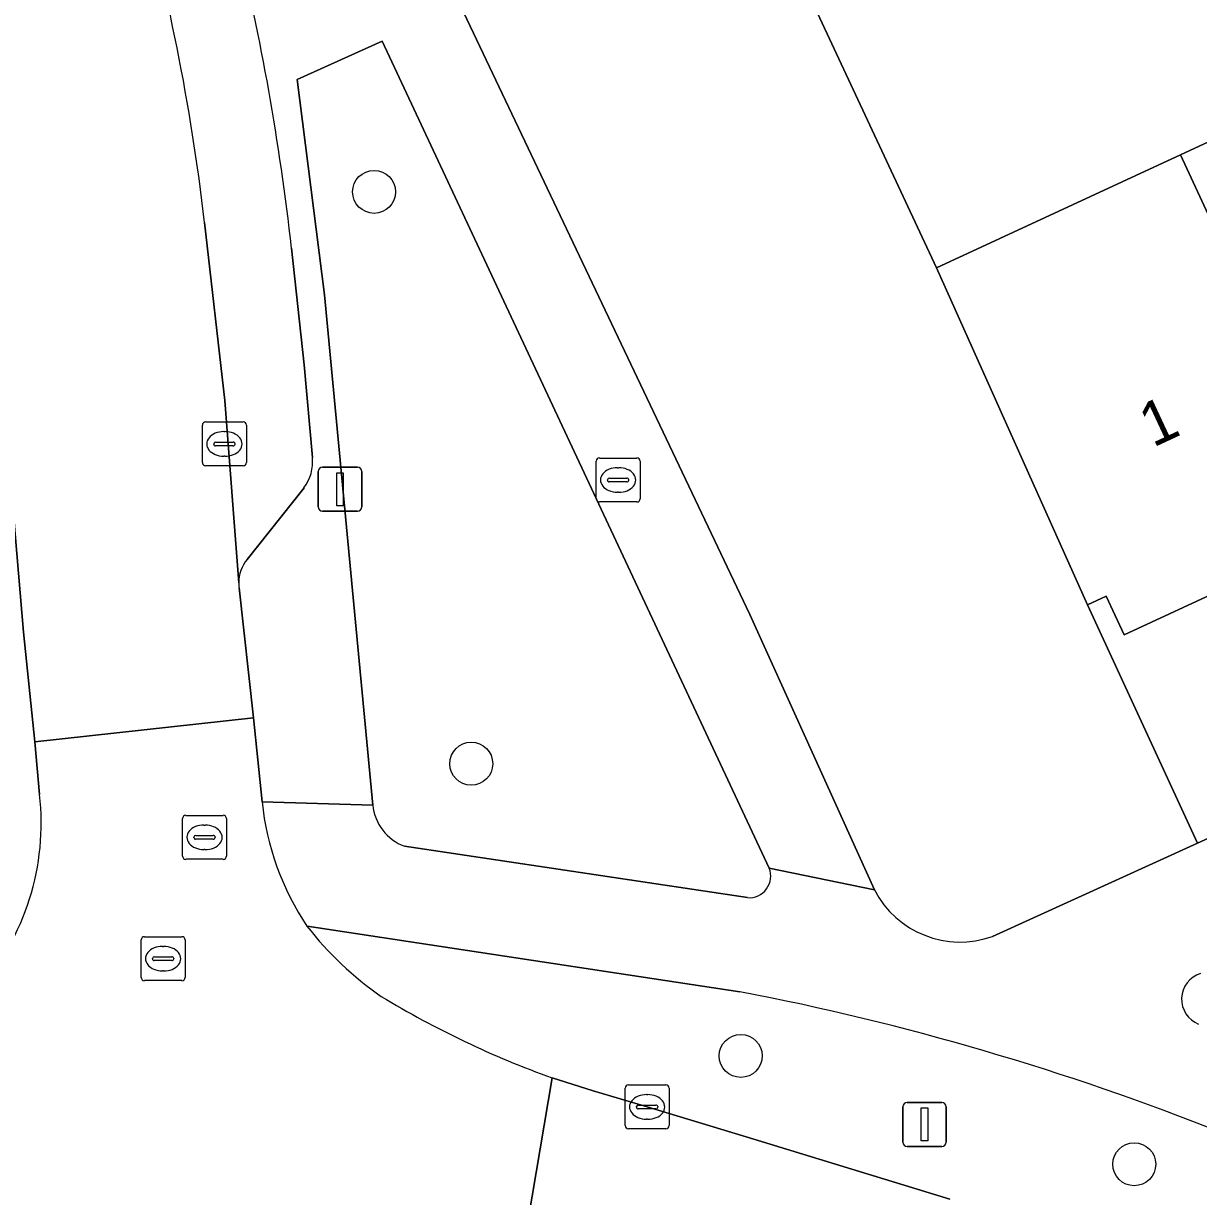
# Model space of a CAD drawing. Extents: x 160030 to 160839, y 385325 to 386450.
# Drawn here: x 160443.86 to 160470.59, y 386074.84 to 386101.52 of the extents above; entities that cross this region are included whole.
import ezdxf

# ---------------------------------------------------------------- set-up
doc = ezdxf.new("R2010")
doc.units = 0
for name, color, linetype in [('IMGEO_Boom', 7, 'Continuous'), ('IMGEO_Brandkraan', 7, 'Continuous'), ('IMGEO_Erf', 7, 'Continuous'), ('IMGEO_Groenvoorziening', 7, 'Continuous'), ('IMGEO_Kolk', 7, 'Continuous'), ('IMGEO_Lichtmast', 7, 'Continuous'), ('IMGEO_Pand', 7, 'Continuous'), ('IMGEO_Pand_nummerreeks', 7, 'Continuous'), ('IMGEO_Parkeervlak_open', 7, 'Continuous'), ('IMGEO_Rijbaan_lokaal_open', 7, 'Continuous'), ('IMGEO_Rioolput', 7, 'Continuous'), ('IMGEO_Voetpad_open', 7, 'Continuous')]:
    doc.layers.add(name, color=color, linetype=linetype)

msp = doc.modelspace()

# ---------------------------------------------------------------- linework, layer by layer
at = {"layer": 'IMGEO_Boom'}
for centre in [(160451.838, 386097.694), (160454.047, 386084.687), (160460.175, 386078.041), (160469.124, 386075.577)]:
    msp.add_circle(centre, 0.489, dxfattribs=at)
at = {"layer": 'IMGEO_Brandkraan'}
for p, q in [((160456.886, 386090.714), (160456.886, 386091.566)), ((160456.961, 386091.64), (160457.813, 386091.64)), ((160457.887, 386091.566), (160457.887, 386090.714)), ((160457.188, 386091.183), (160457.586, 386091.183)), ((160457.374, 386091.42), (160457.399, 386091.42)), ((160457.145, 386091.134), (160457.145, 386091.146)), ((160457.583, 386091.097), (160457.185, 386091.097)), ((160457.629, 386091.146), (160457.629, 386091.134)), ((160457.397, 386090.86), (160457.372, 386090.86)), ((160457.813, 386090.64), (160456.961, 386090.64))]:
    msp.add_line(p, q, dxfattribs=at)
for points in [[(160456.886, 386090.714), (160456.886, 386091.566)], [(160456.961, 386091.64), (160457.813, 386091.64)], [(160457.887, 386091.566), (160457.887, 386090.714)], [(160457.813, 386090.64), (160456.961, 386090.64)]]:
    msp.add_lwpolyline(points, dxfattribs=at)
for centre, radius, start, end in [((160456.963, 386091.564), 0.0765, 91.552, 178.448), ((160456.963, 386091.564), 0.0765, 91.552, 178.448), ((160457.811, 386091.564), 0.0765, 1.552, 88.448), ((160457.811, 386091.564), 0.0765, 1.552, 88.448), ((160457.185, 386091.143), 0.0403, 85.8775, 175.7526), ((160457.59, 386091.145), 0.0386, 1.7309, 96.639), ((160457.182, 386091.133), 0.0366, 178.938, 274.7102), ((160457.586, 386091.14), 0.043, 264.8664, 352.4533), ((160456.963, 386090.716), 0.0765, 181.552, 268.448), ((160456.963, 386090.716), 0.0765, 181.552, 268.448), ((160457.811, 386090.716), 0.0765, 271.552, 358.448), ((160457.811, 386090.716), 0.0765, 271.552, 358.448)]:
    msp.add_arc(centre, radius, start, end, dxfattribs=at)
for centre, major_axis, ratio, start_param, end_param in [((160457.373, 386091.14), (-0.387, 0.002), 0.722429, 4.712389, 7.853982), ((160457.398, 386091.14), (-0.39, 0.002), 0.717154, 1.570796, 4.712389)]:
    msp.add_ellipse(centre, major_axis=major_axis, ratio=ratio, start_param=start_param, end_param=end_param, dxfattribs=at)
at = {"layer": 'IMGEO_Erf'}
for points in [[(160474.661, 386111.537), (160468.204, 386108.702), (160469.751, 386105.389), (160467.465, 386104.321), (160465.268, 386103.296), (160463.721, 386106.609), (160460.404, 386105.012), (160464.625, 386095.964), (160469.161, 386098.069), (160470.175, 386098.539), (160475.678, 386101.093)], [(160472.199, 386089.152), (160468.893, 386087.619), (160468.487, 386088.495), (160468.06, 386088.297), (160470.559, 386082.88), (160479.048, 386086.745)]]:
    msp.add_lwpolyline(points, dxfattribs=at)
at = {"layer": 'IMGEO_Groenvoorziening'}
for points in [[(160464.625, 386095.964), (160460.404, 386105.012), (160453.801, 386101.927), (160460.384, 386088.081), (160463.214, 386081.817)], [(160460.825, 386082.312), (160452.021, 386101.119), (160450.089, 386100.248), (160450.712, 386095.349), (160451.809, 386083.747)], [(160465.902, 386080.76), (160470.559, 386082.88), (160468.06, 386088.297), (160464.625, 386095.964)], [(160452.528, 386082.809), (160460.327, 386081.64)], [(160460.154, 386079.501), (160450.312, 386080.99)], [(160455.889, 386077.541), (160456.822, 386077.249), (160458.047, 386076.88), (160460.475, 386076.143), (160464.932, 386074.783)]]:
    msp.add_lwpolyline(points, dxfattribs=at)
for centre, radius, start, end in [((160452.911, 386083.847), 1.106, 185.1833, 249.7588), ((160460.364, 386082.133), 0.494, 265.6625, 21.2553), ((160465.162, 386082.823), 2.192, 207.3267, 289.7409), ((160456.517, 386085.857), 7.886, 218.108, 235.0637), ((160470.81, 386079.33), 0.609, 107.0053, 248.6087), ((160448.682, 386019.999), 60.598, 68.26831, 79.08732), ((160463.201, 386097.909), 21.641, 238.8319, 250.2517)]:
    msp.add_arc(centre, radius, start, end, dxfattribs=at)
at = {"layer": 'IMGEO_Kolk'}
for p, q in [((160447.932, 386091.534), (160447.932, 386092.386)), ((160448.007, 386092.46), (160448.859, 386092.46)), ((160448.933, 386092.386), (160448.933, 386091.534)), ((160448.234, 386092.003), (160448.632, 386092.003)), ((160448.42, 386092.24), (160448.445, 386092.24)), ((160448.191, 386091.954), (160448.191, 386091.966)), ((160448.629, 386091.917), (160448.231, 386091.917)), ((160448.675, 386091.966), (160448.675, 386091.954)), ((160448.859, 386091.46), (160448.007, 386091.46)), ((160448.443, 386091.68), (160448.418, 386091.68)), ((160457.546, 386076.454), (160457.546, 386077.306)), ((160457.621, 386077.38), (160458.473, 386077.38)), ((160458.547, 386077.306), (160458.547, 386076.454)), ((160458.034, 386077.16), (160458.059, 386077.16)), ((160457.805, 386076.874), (160457.805, 386076.886)), ((160458.243, 386076.837), (160457.845, 386076.837)), ((160457.848, 386076.923), (160458.246, 386076.923)), ((160458.289, 386076.886), (160458.289, 386076.874)), ((160458.057, 386076.6), (160458.032, 386076.6)), ((160458.473, 386076.38), (160457.621, 386076.38))]:
    msp.add_line(p, q, dxfattribs=at)
for points in [[(160447.932, 386091.534), (160447.932, 386092.386)], [(160448.007, 386092.46), (160448.859, 386092.46)], [(160448.933, 386092.386), (160448.933, 386091.534)], [(160448.859, 386091.46), (160448.007, 386091.46)], [(160457.546, 386076.454), (160457.546, 386077.306)], [(160457.621, 386077.38), (160458.473, 386077.38)], [(160458.547, 386077.306), (160458.547, 386076.454)], [(160458.473, 386076.38), (160457.621, 386076.38)]]:
    msp.add_lwpolyline(points, dxfattribs=at)
for centre, radius, start, end in [((160448.009, 386092.384), 0.0765, 91.552, 178.448), ((160448.009, 386092.384), 0.0765, 91.552, 178.448), ((160448.857, 386092.384), 0.0765, 1.552, 88.448), ((160448.857, 386092.384), 0.0765, 1.552, 88.448), ((160448.231, 386091.963), 0.0403, 85.8775, 175.7526), ((160448.636, 386091.965), 0.0386, 1.7309, 96.639), ((160448.228, 386091.953), 0.0366, 178.938, 274.7102), ((160448.632, 386091.96), 0.043, 264.8664, 352.4533), ((160448.009, 386091.536), 0.0765, 181.552, 268.448), ((160448.009, 386091.536), 0.0765, 181.552, 268.448), ((160448.857, 386091.536), 0.0765, 271.552, 358.448), ((160448.857, 386091.536), 0.0765, 271.552, 358.448), ((160457.623, 386077.304), 0.0765, 91.552, 178.448), ((160457.623, 386077.304), 0.0765, 91.552, 178.448), ((160458.471, 386077.304), 0.0765, 1.552, 88.448), ((160458.471, 386077.304), 0.0765, 1.552, 88.448), ((160457.845, 386076.883), 0.0403, 85.8775, 175.7526), ((160457.842, 386076.873), 0.0366, 178.938, 274.7102), ((160458.246, 386076.88), 0.043, 264.8664, 352.4533), ((160458.25, 386076.885), 0.0386, 1.7309, 96.639), ((160457.623, 386076.456), 0.0765, 181.552, 268.448), ((160457.623, 386076.456), 0.0765, 181.552, 268.448), ((160458.471, 386076.456), 0.0765, 271.552, 358.448), ((160458.471, 386076.456), 0.0765, 271.552, 358.448)]:
    msp.add_arc(centre, radius, start, end, dxfattribs=at)
for centre, major_axis, ratio, start_param, end_param in [((160448.419, 386091.96), (-0.387, 0.002), 0.722429, 4.712389, 7.853982), ((160448.444, 386091.96), (-0.39, 0.002), 0.717154, 1.570796, 4.712389), ((160458.033, 386076.88), (-0.387, 0.002), 0.722429, 4.712389, 7.853982), ((160458.058, 386076.88), (-0.39, 0.002), 0.717154, 1.570796, 4.712389)]:
    msp.add_ellipse(centre, major_axis=major_axis, ratio=ratio, start_param=start_param, end_param=end_param, dxfattribs=at)
at = {"layer": 'IMGEO_Lichtmast'}
for p, q in [((160450.568, 386090.53), (160450.568, 386091.33)), ((160450.568, 386091.33), (160450.568, 386090.53)), ((160450.668, 386091.43), (160451.458, 386091.43)), ((160451.458, 386091.43), (160450.668, 386091.43)), ((160451.558, 386091.33), (160451.558, 386090.53)), ((160451.558, 386090.53), (160451.558, 386091.33)), ((160451.458, 386090.43), (160450.668, 386090.43)), ((160450.668, 386090.43), (160451.458, 386090.43)), ((160463.859, 386076.081), (160463.859, 386076.881)), ((160463.859, 386076.881), (160463.859, 386076.081)), ((160463.959, 386076.981), (160464.749, 386076.981)), ((160464.749, 386076.981), (160463.959, 386076.981)), ((160464.849, 386076.881), (160464.849, 386076.081)), ((160464.849, 386076.081), (160464.849, 386076.881)), ((160464.749, 386075.981), (160463.959, 386075.981)), ((160463.959, 386075.981), (160464.749, 386075.981))]:
    msp.add_line(p, q, dxfattribs=at)
for points in [[(160450.988, 386091.305), (160451.138, 386091.305), (160451.138, 386090.555), (160450.988, 386090.555), (160450.988, 386091.305)], [(160464.279, 386076.856), (160464.429, 386076.856), (160464.429, 386076.106), (160464.279, 386076.106), (160464.279, 386076.856)]]:
    msp.add_lwpolyline(points, dxfattribs=at)
for centre, start, end in [((160450.668, 386091.33), 90, 180), ((160450.668, 386091.33), 90, 180), ((160451.458, 386091.33), 0, 90), ((160451.458, 386091.33), 360, 90), ((160450.668, 386090.53), 180, 270), ((160450.668, 386090.53), 180, 270), ((160451.458, 386090.53), 270, 0), ((160451.458, 386090.53), 270, 0), ((160463.959, 386076.881), 90, 180), ((160463.959, 386076.881), 90, 180), ((160464.749, 386076.881), 0, 90), ((160464.749, 386076.881), 360, 90), ((160463.959, 386076.081), 180, 270), ((160463.959, 386076.081), 180, 270), ((160464.749, 386076.081), 270, 0), ((160464.749, 386076.081), 270, 0)]:
    msp.add_arc(centre, 0.1, start, end, dxfattribs=at)
at = {"layer": 'IMGEO_Pand'}
for points in [[(160470.175, 386098.539), (160473.671, 386090.996), (160475.584, 386091.883), (160476.011, 386090.96), (160479.606, 386092.627), (160475.678, 386101.093)], [(160464.625, 386095.964), (160468.06, 386088.297), (160468.487, 386088.495), (160468.893, 386087.619), (160472.199, 386089.152), (160471.756, 386090.108), (160473.671, 386090.996), (160470.175, 386098.539), (160469.161, 386098.069)]]:
    msp.add_lwpolyline(points, close=True, dxfattribs=at)
at = {"layer": 'IMGEO_Parkeervlak_open'}
for points in [[(160443.865, 386087.68), (160443.212, 386095.286), (160442.948, 386097.648)], [(160447.982, 386096.997), (160448.44, 386092.949), (160448.758, 386088.803)], [(160450.436, 386091.651), (160450.245, 386093.762), (160449.961, 386096.41)], [(160448.949, 386089.332), (160450.244, 386090.965)]]:
    msp.add_lwpolyline(points, dxfattribs=at)
for centre, radius, start, end in [((160391.854, 386089.795), 58.485, 10.04637, 17.00413), ((160399.418, 386091.395), 48.886, 6.5797, 16.001), ((160391.996, 386089.854), 58.334, 6.45274, 10.01315), ((160449.452, 386091.556), 0.988, 323.2408, 5.4871), ((160449.589, 386088.802), 0.831, 140.3642, 179.9307)]:
    msp.add_arc(centre, radius, start, end, dxfattribs=at)
at = {"layer": 'IMGEO_Rijbaan_lokaal_open'}
for points in [[(160442.948, 386097.648), (160443.212, 386095.286), (160443.865, 386087.68), (160444.125, 386085.184), (160449.099, 386085.729), (160448.766, 386088.69)], [(160448.758, 386088.803), (160448.44, 386092.949), (160447.982, 386096.997)], [(160449.289, 386083.818), (160449.099, 386085.729), (160444.125, 386085.184), (160444.231, 386083.987)], [(160454.879, 386071.573), (160455.889, 386077.541)], [(160464.932, 386074.783), (160460.475, 386076.143), (160458.047, 386076.88), (160456.822, 386077.249), (160455.889, 386077.541), (160454.879, 386071.573), (160456.59, 386071.254)]]:
    msp.add_lwpolyline(points, dxfattribs=at)
for centre, radius, start, end in [((160399.418, 386091.395), 48.886, 6.5797, 16.001), ((160449.549, 386088.802), 0.791, 179.9436, 188.1555), ((160438.533, 386083.335), 5.735, 270.3865, 6.5305), ((160455.565, 386084.489), 6.312, 186.1048, 213.6693), ((160456.517, 386085.857), 7.886, 218.108, 235.0637), ((160463.201, 386097.909), 21.641, 238.8319, 250.2517)]:
    msp.add_arc(centre, radius, start, end, dxfattribs=at)
at = {"layer": 'IMGEO_Rioolput'}
for p, q in [((160447.481, 386082.586), (160447.481, 386083.438)), ((160447.556, 386083.512), (160448.408, 386083.512)), ((160448.482, 386083.438), (160448.482, 386082.586)), ((160447.969, 386083.292), (160447.994, 386083.292)), ((160447.74, 386083.006), (160447.74, 386083.018)), ((160448.178, 386082.969), (160447.78, 386082.969)), ((160447.783, 386083.055), (160448.181, 386083.055)), ((160448.224, 386083.018), (160448.224, 386083.006)), ((160447.992, 386082.732), (160447.967, 386082.732)), ((160448.408, 386082.512), (160447.556, 386082.512)), ((160446.539, 386079.826), (160446.539, 386080.678)), ((160446.614, 386080.752), (160447.466, 386080.752)), ((160447.027, 386080.532), (160447.052, 386080.532)), ((160447.54, 386080.678), (160447.54, 386079.826)), ((160446.798, 386080.246), (160446.798, 386080.258)), ((160446.841, 386080.295), (160447.239, 386080.295)), ((160447.282, 386080.258), (160447.282, 386080.246)), ((160447.236, 386080.209), (160446.838, 386080.209)), ((160447.05, 386079.972), (160447.025, 386079.972)), ((160447.466, 386079.752), (160446.614, 386079.752))]:
    msp.add_line(p, q, dxfattribs=at)
for points in [[(160447.481, 386082.586), (160447.481, 386083.438)], [(160447.556, 386083.512), (160448.408, 386083.512)], [(160448.482, 386083.438), (160448.482, 386082.586)], [(160448.408, 386082.512), (160447.556, 386082.512)], [(160446.539, 386079.826), (160446.539, 386080.678)], [(160446.614, 386080.752), (160447.466, 386080.752)], [(160447.54, 386080.678), (160447.54, 386079.826)], [(160447.466, 386079.752), (160446.614, 386079.752)]]:
    msp.add_lwpolyline(points, dxfattribs=at)
for centre, radius, start, end in [((160447.558, 386083.436), 0.0765, 91.552, 178.448), ((160447.558, 386083.436), 0.0765, 91.552, 178.448), ((160448.406, 386083.436), 0.0765, 1.552, 88.448), ((160448.406, 386083.436), 0.0765, 1.552, 88.448), ((160447.78, 386083.015), 0.0403, 85.8775, 175.7526), ((160447.777, 386083.005), 0.0366, 178.938, 274.7102), ((160448.181, 386083.012), 0.043, 264.8664, 352.4533), ((160448.185, 386083.017), 0.0386, 1.7309, 96.639), ((160447.558, 386082.588), 0.0765, 181.552, 268.448), ((160447.558, 386082.588), 0.0765, 181.552, 268.448), ((160448.406, 386082.588), 0.0765, 271.552, 358.448), ((160448.406, 386082.588), 0.0765, 271.552, 358.448), ((160446.616, 386080.676), 0.0765, 91.552, 178.448), ((160446.616, 386080.676), 0.0765, 91.552, 178.448), ((160447.464, 386080.676), 0.0765, 1.552, 88.448), ((160447.464, 386080.676), 0.0765, 1.552, 88.448), ((160446.838, 386080.255), 0.0403, 85.8775, 175.7526), ((160446.835, 386080.245), 0.0366, 178.938, 274.7102), ((160447.239, 386080.252), 0.043, 264.8664, 352.4533), ((160447.243, 386080.257), 0.0386, 1.7309, 96.639), ((160446.616, 386079.828), 0.0765, 181.552, 268.448), ((160446.616, 386079.828), 0.0765, 181.552, 268.448), ((160447.464, 386079.828), 0.0765, 271.552, 358.448), ((160447.464, 386079.828), 0.0765, 271.552, 358.448)]:
    msp.add_arc(centre, radius, start, end, dxfattribs=at)
for centre, major_axis, ratio, start_param, end_param in [((160447.968, 386083.012), (-0.387, 0.002), 0.722429, 4.712389, 7.853982), ((160447.993, 386083.012), (-0.39, 0.002), 0.717154, 1.570796, 4.712389), ((160447.026, 386080.252), (-0.387, 0.002), 0.722429, 4.712389, 7.853982), ((160447.051, 386080.252), (-0.39, 0.002), 0.717154, 1.570796, 4.712389)]:
    msp.add_ellipse(centre, major_axis=major_axis, ratio=ratio, start_param=start_param, end_param=end_param, dxfattribs=at)
at = {"layer": 'IMGEO_Voetpad_open'}
for points in [[(160596.696, 386148.006), (160595.267, 386147.385), (160597.535, 386142.364), (160597.404, 386142.014), (160542.981, 386116.622), (160539.966, 386115.215), (160538.304, 386114.44), (160536.242, 386113.478), (160500, 386096.569), (160479.048, 386086.745), (160470.559, 386082.88), (160465.902, 386080.76)], [(160448.766, 386088.69), (160449.099, 386085.729), (160449.289, 386083.818), (160451.809, 386083.747), (160450.712, 386095.349), (160450.089, 386100.248), (160452.021, 386101.119), (160460.825, 386082.312), (160463.214, 386081.817), (160460.384, 386088.081), (160453.801, 386101.927), (160453.089, 386103.425)], [(160449.961, 386096.41), (160450.245, 386093.762), (160450.436, 386091.651)], [(160450.244, 386090.965), (160448.949, 386089.332)], [(160444.231, 386083.987), (160444.125, 386085.184), (160443.865, 386087.68)], [(160451.809, 386083.747), (160449.289, 386083.818)], [(160460.327, 386081.64), (160452.528, 386082.809)], [(160463.214, 386081.817), (160460.825, 386082.312)], [(160450.312, 386080.99), (160460.154, 386079.501)]]:
    msp.add_lwpolyline(points, dxfattribs=at)
for centre, radius, start, end in [((160391.854, 386089.795), 58.485, 10.04637, 17.00413), ((160391.996, 386089.854), 58.334, 6.45274, 10.01315), ((160449.452, 386091.556), 0.988, 323.2408, 5.4871), ((160449.589, 386088.802), 0.831, 140.3642, 179.9307), ((160449.549, 386088.802), 0.791, 179.9436, 188.1555), ((160438.533, 386083.335), 5.735, 270.3865, 6.5305), ((160455.565, 386084.489), 6.312, 186.1048, 213.6693), ((160452.911, 386083.847), 1.106, 185.1833, 249.7588), ((160460.364, 386082.133), 0.494, 265.6625, 21.2553), ((160465.162, 386082.823), 2.192, 207.3267, 289.7409), ((160470.81, 386079.33), 0.609, 107.0053, 248.6087), ((160448.682, 386019.999), 60.598, 68.26831, 79.08732)]:
    msp.add_arc(centre, radius, start, end, dxfattribs=at)

# ---------------------------------------------------------------- texts
at = {"layer": 'IMGEO_Pand_nummerreeks'}
msp.add_text('1', height=1, rotation=25.0051, dxfattribs=at).set_placement((160469.548, 386091.869))

doc.saveas('drawing.dxf')
